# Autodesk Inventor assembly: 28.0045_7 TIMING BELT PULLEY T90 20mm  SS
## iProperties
Created: 2007-04
Part Number: 28.0045_7 TIMING BELT PULLEY T90 20mm  SS
Document SubType Name: Assembly
Designer: Andy Moles
Author: Andy Moles
